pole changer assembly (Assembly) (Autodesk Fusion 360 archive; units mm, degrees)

design "pole changer assembly (Assembly)" references "thimble holder", "combination", "pole changer assembly", "thimble piece", "side panel for middle piece", "wood piece", "cylindrical metal", "underneath rod"
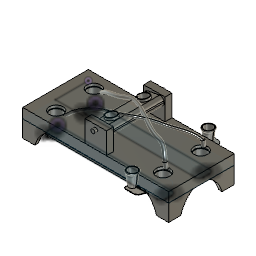
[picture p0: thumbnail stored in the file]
part number: 2026-06-26-15-41-53-289
part number: 2026-06-22-15-23-28-803
part number: 2026-07-01-10-04-10-014
part number: 2026-07-01-10-04-15-208
part number: 2026-07-01-10-11-33-588
component_insert "Component Insert1"
component_insert "Component Insert4"
sketch "Sketch2" plane through (0, 0, 0) normal (0, 1, 0) x axis (1, 0, 0)
  line L1 (27, 0) -> (0, 0)
  line L2 (27, 11.9126) -> (27, 0)
  line L3 (0, 11.9126) -> (27, 11.9126)
  line L4 (0, 0) -> (0, 11.9126)
  point P1 (0, 0)
  point P2 (0, 0)
  point P3 (27, 0)
  point P5 (0, 11.9126)
  horizontal L1
  vertical L2
  horizontal L3
  vertical L4
  coincident P1 P2
  dimension "d5_1" distance P2 P3 = 27
  dimension "d6_1" distance P2 P5 = 11.9126
extrude "Extrude2" new body sketch "Sketch2" along normal blind 71.7804 named "d7_1"
fillet "Fillet1" radius 5 named "d10_1"
sketch "Sketch3" plane through (0, 0, 0) normal (0, -1, 0) x axis (1, 0, 0)
  line L1 (27, -5) -> (27, -6.9126)
  line L2 (5, 0) -> (22, 0)
  line L3 (0, -6.9126) -> (0, -5)
  line L4 (22, -11.9126) -> (5, -11.9126)
  line L5 (22, 0) -> (5, 0)
  line L6 (0, -5) -> (0, -6.9126)
  line L7 (5, -11.9126) -> (22, -11.9126)
  line L8 (27, -6.9126) -> (27, -5)
  line L9 (22, -6.9126) -> (5, -5)
  line L10 (5, -6.9126) -> (22, -6.9126)
  line L11 (22, -5) -> (5, -6.9126)
  line L12 (13.5, 0) -> (13.5, -5.9563)
  line L13 (13.5, -3.341) -> (13.5, 0)
  arc A1 centre (22, -6.9126) radius 5 clockwise from (27, -6.9126) to (22, -11.9126)
  arc A2 centre (22, -5) radius 5 clockwise from (22, 0) to (27, -5)
  arc A3 centre (5, -5) radius 5 clockwise from (0, -5) to (5, 0)
  arc A4 centre (5, -6.9126) radius 5 clockwise from (5, -11.9126) to (0, -6.9126)
  arc A5 centre (5, -5) radius 5 clockwise from (0, -5) to (5, 0)
  arc A6 centre (5, -6.9126) radius 5 clockwise from (5, -11.9126) to (0, -6.9126)
  arc A7 centre (22, -6.9126) radius 5 clockwise from (27, -6.9126) to (22, -11.9126)
  arc A8 centre (22, -5) radius 5 clockwise from (22, 0) to (27, -5)
  circle C1 centre (13.5144, -4.6679) radius 1.327
  point P17 (5, -5)
  point P26 (5, -5)
  point P23 (22, -6.9126)
  point P27 (22, -6.9126)
  point P20 (5, -6.9126)
  point P28 (5, -6.9126)
  point P25 (22, -5)
  point P29 (22, -5)
  point P30 (13.5, -5.9563)
  point P31 (13.5, 0)
  point P32 (13.5, -3.341)
  coincident P17 P26
  coincident P23 P27
  coincident P20 P28
  coincident P25 P29
  midpoint L11 P30
  midpoint L5 P31
  perpendicular L5 L13
  coincident P32 C1
  dimension "d11_1" distance P31 P32 = 3.341
  dimension "d12_1" diameter C1 = 2.654
sketch "Sketch4" plane through (0, 71.7804, 0) normal (0, 1, 0) x axis (-1, 0, 0)
  line L1 (-5, -11.9126) -> (-22, -11.9126)
  line L2 (0, -5) -> (0, -6.9126)
  line L3 (-22, 0) -> (-5, 0)
  line L4 (-27, -6.9126) -> (-27, -5)
  line L5 (-5, -6.9126) -> (-22, -5)
  line L6 (-5, -5) -> (-5, -6.9126)
  line L7 (-22, -6.9126) -> (-5, -5)
  line L8 (-13.5, 0) -> (-13.5, -5.9563)
  line L9 (-13.5, -3.341) -> (-13.5, 0)
  arc A1 centre (-22, -6.9126) radius 5 clockwise from (-22, -11.9126) to (-27, -6.9126)
  arc A2 centre (-5, -6.9126) radius 5 clockwise from (0, -6.9126) to (-5, -11.9126)
  arc A3 centre (-5, -5) radius 5 clockwise from (-5, 0) to (0, -5)
  arc A4 centre (-22, -5) radius 5 clockwise from (-27, -5) to (-22, 0)
  circle C1 centre (-13.5144, -4.6679) radius 1.327
  point P13 (-22, -5)
  point P14 (-22, -5)
  point P7 (-5, -6.9126)
  point P15 (-5, -6.9126)
  point P10 (-5, -5)
  point P16 (-5, -5)
  point P4 (-22, -6.9126)
  point P17 (-22, -6.9126)
  point P18 (-13.5, -5.9563)
  point P19 (-13.5, 0)
  point P20 (-13.5, -3.341)
  coincident P13 P14
  coincident P7 P15
  coincident P10 P16
  coincident P4 P17
  midpoint L5 P18
  midpoint L3 P19
  perpendicular L3 L9
  coincident P20 C1
  dimension "d15" distance P19 P20 = 3.341
  dimension "d16" diameter C1 = 2.654
sketch "Sketch5" plane through (0, 0, 0) normal (0, 0, 1) x axis (-1, 0, 0)
  line L1 (-22, -71.7804) -> (-22, 0)
  line L2 (-5, -71.7804) -> (-22, -71.7804)
  line L3 (-5, 0) -> (-5, -71.7804)
  line L4 (-22, 0) -> (-5, 0)
  line L5 (-13.5, -6) -> (-13.5, 0)
  line L6 (-13.5, -65.7804) -> (-13.5, -71.7804)
  circle C1 centre (-13.5, -13.5) radius 7.5
  circle C2 centre (-13.5, -58.2804) radius 7.5
  circle C3 centre (-13.5, -13.5) radius 6.5
  circle C4 centre (-13.5, -58.2804) radius 6.5
  point P6 (-13.5, 0)
  point P8 (-13.5, -71.7804)
  point P7 (-13.5, -6)
  point P9 (-13.5, -65.7804)
  midpoint L4 P6
  perpendicular L4 L5
  midpoint L2 P8
  perpendicular L2 L6
  coincident P7 C1
  coincident P9 C2
  concentric C1 C3
  concentric C2 C4
  dimension "d19" distance P8 P9 = 6
  dimension "d20" diameter C1 = 15
  dimension "d21" diameter C2 = 15
  dimension "d22" diameter C3 = 13
  dimension "d23" diameter C4 = 13
extrude "Extrude5" add sketch "Sketch5" profile of C1 C2 C3 C4 along normal blind 3 named "d24_1"
extrude "Extrude6" cut of existing geometry blind -6 named "d26_1"
component_insert "Component Insert6"
component_insert "Component Insert7"
component_insert "Component Insert8"
component_insert "Component Insert9"
component_insert "Component Insert10"
component_insert "Component Insert11"
component_insert "Component Insert12"
component_insert "Component Insert13"
position "Position1"
sketch "Sketch1" plane through (0, 0, -13.716) normal (0, 0, -1) x axis (1, 0, 0)
  line L1 (0, 91.44) -> (203.2, 91.44)
  line L2 (0, 0) -> (0, 91.44)
  line L3 (203.2, 0) -> (0, 0)
  line L4 (203.2, 91.44) -> (203.2, 0)
  line L5 (0, 45.72) -> (0, 0)
  line L6 (38, 45.72) -> (0, 45.72)
  circle C1 centre (27.2669, 19.4754) radius 9.525
  circle C2 centre (175.9331, 19.4754) radius 9.525
  circle C3 centre (175.9331, 71.9646) radius 9.525
  circle C4 centre (27.2669, 71.9646) radius 9.525
  point P1 (0, 0)
  point P10 (0, 0)
  point P11 (0, 45.72)
  point P12 (38, 45.72)
  coincident P1 P10
  perpendicular L3 L5
  perpendicular L5 L6
  dimension "d1" distance P10 P11 = 45.72
  dimension "d2" distance P11 P12 = 38
component_insert "Component Insert14"
component_insert "Component Insert15"
position "Position2"
sketch "Sketch2" plane through (0, 0, 0) normal (0, 0, 1) x axis (-1, 0, 0)
  line L1 (-203.2, 91.44) -> (0, 91.44)
  line L2 (-203.2, 0) -> (-203.2, 91.44)
  line L3 (0, 0) -> (-203.2, 0)
  line L4 (0, 91.44) -> (0, 0)
  line L5 (-25.5453, 9.5513) -> (-177.6547, 9.5513)
  line L6 (-19.5453, 23.3887) -> (-19.5453, 15.5513)
  line L7 (-177.6547, 29.3887) -> (-25.5453, 29.3887)
  line L8 (-183.6547, 15.5513) -> (-183.6547, 23.3887)
  line L9 (-183.6547, 23.3887) -> (-183.6547, 15.5513)
  line L10 (-25.5453, 29.3887) -> (-177.6547, 29.3887)
  line L11 (-19.5453, 15.5513) -> (-19.5453, 23.3887)
  line L12 (-177.6547, 9.5513) -> (-25.5453, 9.5513)
  line L13 (0, 91.44) -> (-203.2, 91.44)
  line L14 (0, 0) -> (0, 91.44)
  line L15 (-203.2, 0) -> (0, 0)
  line L16 (-203.2, 91.44) -> (-203.2, 0)
  curve K1 (-175.9331, 71.9646) -> (-27.2669, 19.4754)
  curve K2 (-27.2669, 71.9646) -> (-175.9331, 19.4755)
  curve K3 (-128.5697, 42.4076) -> (-150.1136, 28.6028)
  curve K4 (-160.0793, 60.7438) -> (-134.7391, 51.89)
  curve K5 (-141.9601, 34.3106) -> (-176.1345, 18.4891)
  circle C1 centre (-27.2669, 19.4754) radius 9.525
  circle C2 centre (-27.2669, 71.9646) radius 9.525
  circle C3 centre (-175.9331, 19.4754) radius 9.525
  circle C4 centre (-175.9331, 71.9646) radius 9.525
  circle C5 centre (-27.2669, 19.4754) radius 2.5
  circle C6 centre (-175.9331, 71.9646) radius 2.5
  circle C7 centre (-27.2669, 19.4754) radius 8.525
  circle C8 centre (-27.2669, 19.4754) radius 9.525
  arc A1 centre (-177.6547, 15.5513) radius 6 clockwise from (-177.6547, 9.5513) to (-183.6547, 15.5513)
  arc A2 centre (-25.5453, 15.5513) radius 6 clockwise from (-19.5453, 15.5513) to (-25.5453, 9.5513)
  arc A3 centre (-25.5453, 23.3887) radius 6 clockwise from (-25.5453, 29.3887) to (-19.5453, 23.3887)
  arc A4 centre (-177.6547, 23.3887) radius 6 clockwise from (-183.6547, 23.3887) to (-177.6547, 29.3887)
  arc A5 centre (-177.6547, 15.5513) radius 6 clockwise from (-177.6547, 9.5513) to (-183.6547, 15.5513)
  arc A6 centre (-177.6547, 23.3887) radius 6 clockwise from (-183.6547, 23.3887) to (-177.6547, 29.3887)
  arc A7 centre (-25.5453, 23.3887) radius 6 clockwise from (-25.5453, 29.3887) to (-19.5453, 23.3887)
  arc A8 centre (-25.5453, 15.5513) radius 6 clockwise from (-19.5453, 15.5513) to (-25.5453, 9.5513)
  circle C9 centre (-27.2669, 19.4754) radius 9.525
  circle C10 centre (-27.2669, 19.4754) radius 8.525
  circle C11 centre (-27.2669, 19.4754) radius 8.525
  circle C12 centre (-27.2669, 19.4754) radius 9.525
  circle C13 centre (-27.2669, 19.4754) radius 9.525
  circle C14 centre (-27.2669, 19.4754) radius 9.525
  circle C15 centre (-27.2669, 19.4754) radius 9.525
  circle C16 centre (-27.2669, 19.4754) radius 9.525
  circle C17 centre (-175.9331, 19.4754) radius 9.525
  circle C18 centre (-175.9331, 71.9646) radius 9.525
  circle C19 centre (-27.2669, 71.9646) radius 9.525
  circle C20 centre (-175.9331, 19.4754) radius 2.5
  circle C21 centre (-27.2669, 71.9646) radius 2.5
  point P10 (-27.2669, 19.4754)
  point P53 (-27.2669, 19.4754)
  point P11 (-175.9331, 71.9646)
  point P59 (-175.9331, 71.9646)
  point P60 (-175.9331, 19.4754)
  point P62 (-175.9331, 19.4755)
  point P61 (-27.2669, 71.9646)
  point P69 (-27.2669, 71.9646)
  point P64 (-139.3417, 35.5052)
  point P57 (-147.4092, 56.3169)
  point P63 (-159.0473, 26.3999)
  concentric C1 C5
  concentric C4 C6
  coincident P10 P53
  coincident P11 P59
  concentric C3 C20
  concentric C2 C21
  coincident P60 P62
  coincident P61 P69
  midpoint P64 K3
  midpoint P57 K4
  midpoint P63 K5
  dimension "d3" diameter C5 = 5
  dimension "d4" diameter C6 = 5
  dimension "d5" diameter C20 = 5
  dimension "d6" diameter C21 = 5
loft "Loft2" sketch "Sketch2"
loft "Loft3" sketch "Sketch2"
extrude "Extrude1" add sketch "Sketch2" profile of C21 against normal blind 8
extrude "Extrude2" add sketch "Sketch2" profile of C5 C20 against normal blind 8
extrude "Extrude3" add sketch "Sketch2" profile of C6 against normal blind 8
component_insert "Component Insert16"
position "Position3"
mirror_component "MirrorComponent1"
derived_instance "DerivedInstance1"
sketch "Sketch3" plane through (0, -81.6102, 0) normal (0, -1, 0) x axis (1, 0, 0)
  line L1 (115.1, 21.9126) -> (115.1, 20)
  line L2 (93.1, 26.9126) -> (110.1, 26.9126)
  line L3 (88.1, 20) -> (88.1, 21.9126)
  line L4 (110.1, 15) -> (93.1, 15)
  circle C1 centre (101.6037, 25.1585) radius 1.3313
  arc A1 centre (110.1, 20) radius 5 clockwise from (115.1, 20) to (110.1, 15)
  arc A2 centre (110.1, 21.9126) radius 5 clockwise from (110.1, 26.9126) to (115.1, 21.9126)
  arc A3 centre (93.1, 21.9126) radius 5 clockwise from (88.1, 21.9126) to (93.1, 26.9126)
  arc A4 centre (93.1, 20) radius 5 clockwise from (93.1, 15) to (88.1, 20)
sketch "Sketch4" plane through (0, -9.8298, 0) normal (0, 1, 0) x axis (-1, 0, 0)
  line L1 (-93.1, 15) -> (-110.1, 15)
  line L2 (-88.1, 21.9126) -> (-88.1, 20)
  line L3 (-110.1, 26.9126) -> (-93.1, 26.9126)
  line L4 (-115.1, 20) -> (-115.1, 21.9126)
  circle C1 centre (-101.6, 25.15) radius 1.35
  arc A1 centre (-110.1, 20) radius 5 clockwise from (-110.1, 15) to (-115.1, 20)
  arc A2 centre (-93.1, 20) radius 5 clockwise from (-88.1, 20) to (-93.1, 15)
  arc A3 centre (-93.1, 21.9126) radius 5 clockwise from (-93.1, 26.9126) to (-88.1, 21.9126)
  arc A4 centre (-110.1, 21.9126) radius 5 clockwise from (-115.1, 21.9126) to (-110.1, 26.9126)
as_built_joint "As-built5" OffsetX 0 OffsetY 0 OffsetZ 0 AngleZ 0 RotateMinimum -8 RotateMaximum 8
component_from_bodies "Body->Comp1"
component_from_bodies "Body->Comp2"
as_built_joint "As-built8"
copy_paste "CutPaste1"
copy_paste "CutPaste2"
sketch "Sketch5" plane through (0, -91.2914, 0) normal (0, -1, 0) x axis (1, 0, 0)
  line L1 (86.6775, 0) -> (86.6775, 29.845)
  line L2 (116.5225, 0) -> (86.6775, 0)
  line L3 (116.5225, 29.845) -> (116.5225, 0)
  line L4 (86.6775, 29.845) -> (116.5225, 29.845)
  circle C1 centre (101.6, 23.837) radius 2.667
  circle C2 centre (101.6, 23.837) radius 1.35
  concentric C1 C2
extrude "Extrude6" new body sketch "Sketch5" profile of C1 C2 along normal blind 6
sketch "Sketch6" plane through (0, -0.1486, 0) normal (0, 1, 0) x axis (-1, 0, 0)
  line L1 (-53.6775, 72.39) -> (-53.6775, 42.545)
  line L2 (-83.5225, 72.39) -> (-53.6775, 72.39)
  line L3 (-83.5225, 42.545) -> (-83.5225, 72.39)
  line L4 (-53.6775, 42.545) -> (-83.5225, 42.545)
  circle C1 centre (-68.6, 66.382) radius 2.667
  circle C2 centre (-68.6, 66.382) radius 1.35
  concentric C1 C2
extrude "Extrude7" new body sketch "Sketch6" profile of C1 C2 along normal blind 6
extrude "Extrude8" cut of existing geometry blind -2
extrude "Extrude9" cut of existing geometry blind -2
component_insert "Component Insert17"
move "Move1"
move "Move2"
component_insert "Component Insert18"
position "Position4"
component_insert "Component Insert19"
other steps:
base_feature "Base Feature1"
base_feature "Base Feature1"
derived_base_feature "Derived Base Feature" sketch "Sketch2"
create_component "CreateComponent1"
create_component "CreateComponent2"
create_component "CreateComponent3"
reparent_decal "ReparentDecal2"
remove_body "RemoveBody2"
create_component "CreateComponent4"
remove_instance "RemoveInstance1"
remove_instance "RemoveInstance2"
reparent_decal "ReparentDecal3"
remove_body "RemoveBody3"

design "Side panel for the top of Pole Changer" references "autodesk 3ax table xy head z"
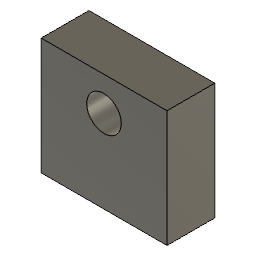
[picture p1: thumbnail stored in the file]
part number: 2026-03-06-14-36-18-397
sketch "Sketch1" plane through (0, 0, 0) normal (0, 0, 1) x axis (1, 0, 0)
  line L1 (32.385, 0) -> (0, 0)
  line L2 (32.385, 12.319) -> (32.385, 0)
  line L3 (0, 12.319) -> (32.385, 12.319)
  line L4 (0, 0) -> (0, 12.319)
  point P1 (0, 0)
  point P2 (0, 0)
  point P3 (32.385, 0)
  point P5 (0, 12.319)
  horizontal L1
  vertical L2
  horizontal L3
  vertical L4
  coincident P1 P2
  dimension "d1" distance P2 P3 = 32.385
  dimension "d2" distance P2 P5 = 12.319
extrude "Extrude1" new body sketch "Sketch1" along normal blind 30.0482
sketch "Sketch2" plane through (0, 0, 0) normal (0, -1, 0) x axis (1, 0, 0)
  line L1 (32.385, 0) -> (0, 0)
  line L2 (32.385, 30.0482) -> (32.385, 0)
  line L3 (0, 30.0482) -> (32.385, 30.0482)
  line L4 (0, 0) -> (0, 30.0482)
  circle C1 centre (16.1726, 21.3291) radius 4.445
  dimension "d5" diameter C1 = 8.89
extrude "Extrude2" cut sketch "Sketch2" profile of C1 against normal blind 12.319

design "cylindrical metal"
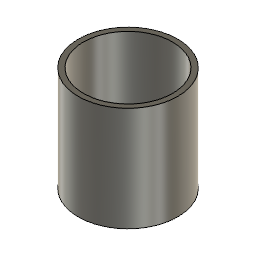
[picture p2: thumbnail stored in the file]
part number: 2026-06-29-10-16-31-492
sketch "Sketch1" plane through (0, 0, 0) normal (0, 0, 1) x axis (1, 0, 0)
  circle C1 centre (0, 0) radius 9.525
  point P1 (0, 0)
  point P2 (0, 0)
  coincident P1 P2
  dimension "d1" diameter C1 = 19.05
extrude "Extrude1" new body sketch "Sketch1" along normal blind 20
shell "Shell1" innerThickness 1

design "thimble piece"
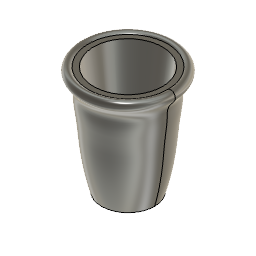
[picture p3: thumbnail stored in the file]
part number: 2026-06-22-15-23-28-803
sketch "Sketch2" plane through (0, 0, 0) normal (0, 1, 0) x axis (1, 0, 0)
  line L1 (17.6024, 0) -> (0, 0)
  line L2 (17.6024, -7) -> (17.6024, 0)
  curve K1 (22, -13) -> (17.6024, -7)
  curve K2 (21.2743, -12.5102) -> (16.7269, -7.4605)
  line L3 (16.7269, -7.4605) -> (16.7269, -0.8755)
  line L4 (16.7269, -0.8755) -> (0.8755, -0.8755)
  line L5 (0, 0) -> (0.8755, -0.8755)
  line L6 (22, -13) -> (21.2743, -12.5102)
  point P1 (0, 0)
  point P2 (0, 0)
  point P3 (17.6024, 0)
  point P4 (17.6024, -7)
  coincident P1 P2
  perpendicular L1 L2
  dimension "d1" distance P3 P4 = 7
  dimension "d2" = 0.8755
sketch "Sketch4" plane through (0, 0, 0) normal (0, 1, 0) x axis (1, 0, 0)
  line L1 (4.655, 0) -> (0, 0)
  curve K1 (6.9446, -18.8982) -> (4.655, 0)
  line L2 (6.0248, -18.8982) -> (6.9446, -18.8982)
  line L3 (3.5953, -1.1464) -> (6.0248, -18.8982)
  line L4 (0, -1.1464) -> (3.5953, -1.1464)
  line L5 (0, 0) -> (0, -1.1464)
  point P1 (0, 0)
  point P2 (0, 0)
  coincident P1 P2
  horizontal L1
  horizontal L2
  parallel L1 L4
  perpendicular L1 L5
revolve "Revolve2" sketch "Sketch4" AlongAngle 360

design "side panel for middle piece"
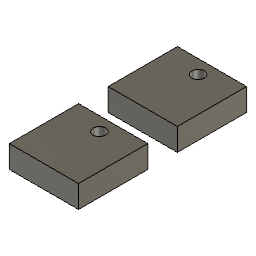
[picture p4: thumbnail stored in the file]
part number: 2026-06-23-11-54-25-800
sketch "Sketch1" plane through (0, 0, 0) normal (0, 1, 0) x axis (1, 0, 0)
  line L1 (29.845, 0) -> (0, 0)
  line L2 (29.845, 29.845) -> (29.845, 0)
  line L3 (0, 29.845) -> (29.845, 29.845)
  line L4 (0, 0) -> (0, 29.845)
  point P1 (0, 0)
  point P2 (0, 0)
  point P3 (29.845, 0)
  point P5 (0, 29.845)
  horizontal L1
  vertical L2
  horizontal L3
  vertical L4
  coincident P1 P2
  dimension "d1" distance P2 P3 = 29.845
  dimension "d2" distance P2 P5 = 29.845
extrude "Extrude1" new body sketch "Sketch1" along normal blind 9.7028
sketch "Sketch2" plane through (0, 0, 0) normal (0, -1, 0) x axis (1, 0, 0)
  line L1 (0, -29.845) -> (0, 0)
  line L2 (29.845, -29.845) -> (0, -29.845)
  line L3 (29.845, 0) -> (29.845, -29.845)
  line L4 (0, 0) -> (29.845, 0)
  line L5 (29.845, -29.845) -> (0, 0)
  line L6 (0, -29.845) -> (29.845, 0)
  line L7 (14.9225, 0) -> (14.9225, -14.9225)
  line L8 (14.9225, -3.341) -> (14.9225, 0)
  circle C1 centre (14.9225, -6.008) radius 2.667
  point P1 (0, 0)
  point P6 (0, 0)
  point P4 (29.845, -29.845)
  point P7 (29.845, -29.845)
  point P5 (29.845, 0)
  point P8 (29.845, 0)
  point P3 (0, -29.845)
  point P9 (0, -29.845)
  point P10 (14.9225, -14.9225)
  point P11 (14.9225, 0)
  point P12 (14.9225, -3.341)
  coincident P1 P6
  coincident P4 P7
  coincident P5 P8
  coincident P3 P9
  midpoint L6 P10
  midpoint L4 P11
  perpendicular L4 L8
  coincident P12 C1
  dimension "d5" distance P11 P12 = 3.341
  dimension "d6" diameter C1 = 5.334
extrude "Extrude2" cut sketch "Sketch2" profile of L7 C1 against normal blind 27
sketch "Sketch3" plane through (0, 0, 0) normal (0, 1, 0) x axis (1, 0, 0)
copy_paste_bodies "CopyPasteBodies1"
move "Move1"
move "Move2"
move "Move3"
move "Move4"
move "Move5"
move "Move6"
move "Move7"
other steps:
base_feature "Base Feature"

design "thimble holder"
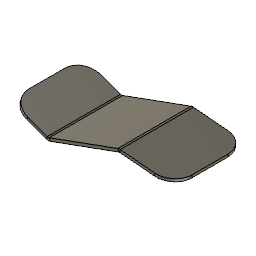
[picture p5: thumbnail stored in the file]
part number: 2026-06-23-10-44-33-506
parameter "d6" = 0.762
sketch "Sketch1" plane through (0, 0, 0) normal (0, 0, 1) x axis (1, 0, 0)
  line L1 (40.4406, 0) -> (5, 0)
  line L2 (45.4406, -14.558) -> (45.4406, -5)
  line L3 (5, -19.558) -> (40.4406, -19.558)
  line L4 (0, -5) -> (0, -14.558)
  arc A1 centre (5, -5) radius 5 clockwise from (0, -5) to (5, 0)
  arc A2 centre (5, -14.558) radius 5 clockwise from (5, -19.558) to (0, -14.558)
  arc A3 centre (40.4406, -14.558) radius 5 clockwise from (45.4406, -14.558) to (40.4406, -19.558)
  arc A4 centre (40.4406, -5) radius 5 clockwise from (40.4406, 0) to (45.4406, -5)
  point P1 (0, 0)
  point P2 (0, 0)
  point P4 (0, -19.558)
  point P3 (45.4406, 0)
  horizontal L1
  vertical L2
  horizontal L3
  vertical L4
  coincident P1 P2
  coincident P2 L1
  coincident P2 L4
  tangent L1 A1
  tangent L4 A1
  coincident P4 L3
  coincident P4 L4
  tangent L3 A2
  tangent L4 A2
  equal A1 A2
  tangent L2 A3
  tangent L3 A3
  equal A1 A3
  coincident P3 L1
  coincident P3 L2
  tangent L1 A4
  tangent L2 A4
  equal A1 A4
  dimension "d1" distance P2 P3 = 45.4406
  dimension "d2" distance P2 P4 = 19.558
  dimension "d3" radius A1 = 5
extrude "Extrude1" new body sketch "Sketch1" along normal blind 0.762
sketch "Sketch2" plane through (0, 0, 0) normal (0, 0, 1) x axis (1, 0, 0)
step "ConvertToSheetMetal"
sketch "Sketch3" plane through (0, 0, 0.762) normal (0, 0, 1) x axis (-1, 0, 0)
  line L1 (-45.4406, 5) -> (-45.4406, 14.558)
  line L2 (-5, 0) -> (-40.4406, 0)
  line L3 (0, 14.558) -> (0, 5)
  line L4 (-40.4406, 19.558) -> (-5, 19.558)
  line L5 (-11.2867, 0) -> (-11.2867, 19.558)
  line L6 (-30.7215, 0) -> (-30.7215, 19.558)
  arc A1 centre (-40.4406, 14.558) radius 5 clockwise from (-45.4406, 14.558) to (-40.4406, 19.558)
  arc A2 centre (-40.4406, 5) radius 5 clockwise from (-40.4406, 0) to (-45.4406, 5)
  arc A3 centre (-5, 5) radius 5 clockwise from (0, 5) to (-5, 0)
  arc A4 centre (-5, 14.558) radius 5 clockwise from (-5, 19.558) to (0, 14.558)
  point P14 (-11.2867, 19.558)
  point P15 (-11.2867, 0)
  point P16 (-30.7215, 19.558)
  point P17 (-30.7215, 0)
  coincident L4 P14
  coincident L2 P15
  perpendicular L2 L5
  coincident L4 P16
  coincident L2 P17
  perpendicular L2 L6
step "Fold" BendAngle -25 BendAngle 40
move "Move2"

design "wood piece"
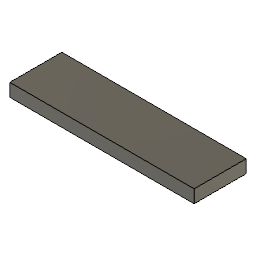
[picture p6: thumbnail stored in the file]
part number: 2026-06-29-10-46-20-872
sketch "Sketch1" plane through (0, 0, 0) normal (0, 0, 1) x axis (1, 0, 0)
  line L1 (127.2, 0) -> (0, 0)
  line L2 (127.2, 36) -> (127.2, 0)
  line L3 (0, 36) -> (127.2, 36)
  line L4 (0, 0) -> (0, 36)
  point P1 (0, 0)
  point P2 (0, 0)
  point P3 (127.2, 0)
  point P5 (0, 36)
  horizontal L1
  vertical L2
  horizontal L3
  vertical L4
  coincident P1 P2
  dimension "d1" distance P2 P3 = 127.2
  dimension "d2" distance P2 P5 = 36
extrude "Extrude1" new body sketch "Sketch1" along normal blind 9

design "autodesk 3ax table xy head z"
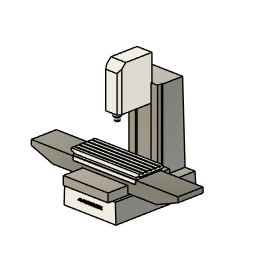
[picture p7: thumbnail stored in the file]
named bodies: "x_axis_table", "y_axis_table", "z_axis_head", "Base"

design "base plate"
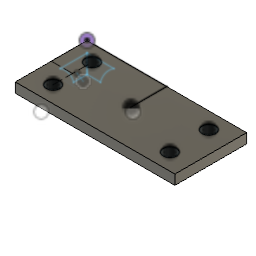
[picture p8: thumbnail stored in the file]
part number: 2026-06-18-10-46-35-977
sketch "Sketch1" plane through (0, 0, 0) normal (0, 0, 1) x axis (1, 0, 0)
  line L1 (203.2, 0) -> (0, 0)
  line L2 (203.2, -91.44) -> (203.2, 0)
  line L3 (0, -91.44) -> (203.2, -91.44)
  line L4 (0, 0) -> (0, -91.44)
  point P1 (0, 0)
  point P2 (0, 0)
  point P3 (203.2, 0)
  point P5 (0, -91.44)
  horizontal L1
  vertical L2
  horizontal L3
  vertical L4
  coincident P1 P2
  dimension "d1" distance P2 P3 = 203.2
  dimension "d2" distance P2 P5 = 91.44
extrude "Extrude1" new body sketch "Sketch1" against normal blind 12.573
sketch "Sketch2" plane through (0, 0, 0) normal (0, 1, 0) x axis (1, 0, 0)
  line L1 (0, 37.5458) -> (0, 14)
  line L2 (17.0307, 37.5458) -> (0, 37.5458)
  line L3 (34.0614, 14) -> (0, 14)
  arc A1 centre (58.4006, 49.5366) radius 43.0726 clockwise from (34.0614, 14) to (17.0307, 37.5458)
  point P2 (0, 14)
  point P3 (0, 37.5458)
  point P4 (17.0307, 37.5458)
  point P5 (34.0614, 14)
  vertical L1
  perpendicular L1 L2
  perpendicular L1 L3
  dimension "d5" distance P2 P3 = 23.5458
  dimension "d6" distance P3 P4 = 17.0307
  dimension "d7" distance P2 P5 = 34.0614
sketch "Sketch4" plane through (0, 0, 0) normal (0, 1, 0) x axis (1, 0, 0)
  dimension "d8" = 23.5458
  dimension "d9" = 17.0307
  dimension "d10" = 34.0614
extrude "Extrude2" new body sketch "Sketch2" against normal blind 12.573
sketch "Sketch6" plane through (0, 0, -37.5458) normal (0, 0, -1) x axis (1, 0, 0)
  line L1 (17.0307, 0) -> (0, 0)
  line L2 (17.0307, 12.573) -> (17.0307, 0)
  line L3 (0, 12.573) -> (17.0307, 12.573)
  line L4 (0, 0) -> (0, 12.573)
  line L5 (12.573, 12.573) -> (0, 0)
  point P1 (0, 0)
  point P6 (0, 0)
  point P7 (12.573, 12.573)
  coincident P1 P6
  coincident L3 P7
copy_paste_bodies "CopyPasteBodies1"
move "Move1"
sketch "Sketch7" plane through (0, 0, -37.5458) normal (0, 0, -1) x axis (1, 0, 0)
  line L1 (5, 22.0307) -> (5, 5)
  line L2 (-7.573, 22.0307) -> (5, 22.0307)
  line L3 (-7.573, 5) -> (-7.573, 22.0307)
  line L4 (5, 5) -> (-7.573, 5)
  line L5 (5, 10) -> (-7.573, 5)
  point P5 (-7.573, 5)
  point P6 (-7.573, 5)
  point P7 (5, 10)
  coincident P5 P6
  coincident L1 P7
extrude "Extrude3" cut sketch "Sketch6" profile of L3 L4 L5 against normal blind 23.546
extrude "Extrude4" cut sketch "Sketch7" profile of L1 L4 L5 against normal blind 23.546
move "Move2"
sketch "Sketch9" plane through (0, 0, 0) normal (0, 0, 1) x axis (1, 0, 0)
  line L1 (27.2669, -20.955) -> (27.2669, -70.485)
  line L2 (0, -45.72) -> (0, 0)
  line L3 (27.2669, -45.72) -> (0, -45.72)
  line L4 (101.6, 0) -> (0, 0)
  line L5 (101.6, -45.72) -> (101.6, 0)
  circle C1 centre (27.2669, -70.485) radius 8.35
  circle C2 centre (27.2669, -20.955) radius 8.35
  circle C3 centre (175.9331, -20.955) radius 8.35
  circle C4 centre (175.9331, -70.485) radius 8.35
  point P2 (27.2669, -70.485)
  point P4 (27.2669, -70.485)
  point P3 (27.2669, -20.955)
  point P5 (27.2669, -20.955)
  point P1 (0, 0)
  point P6 (0, 0)
  point P8 (27.2669, -45.72)
  point P7 (0, -45.72)
  point P9 (101.6, 0)
  point P10 (101.6, -45.72)
  point P11 (175.9331, -20.955)
  coincident P2 P4
  coincident P3 P5
  vertical L1
  coincident P1 P6
  vertical L2
  coincident L1 P8
  perpendicular L1 L3
  symmetric P2 P3 L3
  horizontal L4
  perpendicular L4 L5
  symmetric C1 L5 C4
  symmetric C2 L5 C3
  dimension "d17" diameter C1 = 16.7
  dimension "d18" diameter C2 = 16.7
  dimension "d19" distance P2 P3 = 49.53
  dimension "d20" distance P6 P7 = 45.72
  dimension "d21" distance P6 P9 = 101.6
  dimension "d22" distance P9 P10 = 45.72
  dimension "d23" distance P3 P11 = 148.6662
extrude "Extrude5" cut sketch "Sketch9" profile of C1 C2 C3 C4 against normal blind 7.5
extrude "Extrude6" cut sketch "Sketch9" profile of C1 C2 C3 C4 against normal blind 45
combine "Combine2"
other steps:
base_feature "Base Feature"
step "WorkPlane" RotateAngle -45

design "underneath rod"
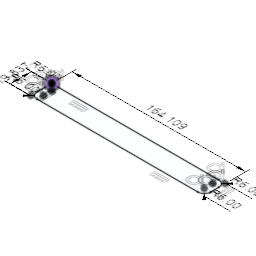
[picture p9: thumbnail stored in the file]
part number: 2026-06-22-13-07-32-892
sketch "Sketch1" plane through (0, 0, 0) normal (0, 0, 1) x axis (1, 0, 0)
  line L1 (158.1094, 0) -> (6, 0)
  line L2 (164.1094, -13.8374) -> (164.1094, -6)
  line L3 (6, -19.8374) -> (158.1094, -19.8374)
  line L4 (0, -6) -> (0, -13.8374)
  arc A1 centre (158.1094, -6) radius 6 clockwise from (158.1094, 0) to (164.1094, -6)
  arc A2 centre (158.1094, -13.8374) radius 6 clockwise from (164.1094, -13.8374) to (158.1094, -19.8374)
  arc A3 centre (6, -13.8374) radius 6 clockwise from (6, -19.8374) to (0, -13.8374)
  arc A4 centre (6, -6) radius 6 clockwise from (0, -6) to (6, 0)
  point P1 (0, 0)
  point P2 (0, 0)
  point P3 (164.1094, 0)
  point P4 (0, -19.8374)
  horizontal L1
  vertical L2
  horizontal L3
  vertical L4
  coincident P1 P2
  coincident P3 L1
  coincident P3 L2
  tangent L1 A1
  tangent L2 A1
  tangent L2 A2
  tangent L3 A2
  coincident P4 L3
  coincident P4 L4
  tangent L3 A3
  tangent L4 A3
  coincident P2 L4
  coincident P2 L1
  tangent L4 A4
  tangent L1 A4
  dimension "d1" distance P2 P3 = 164.1094
  dimension "d2" distance P2 P4 = 19.8374
  dimension "d5" radius A1 = 6
  dimension "d6" radius A2 = 6
  dimension "d7" radius A3 = 6
  dimension "d8" radius A4 = 6
extrude "Extrude2" new body sketch "Sketch1" along normal blind 2.6162
sketch "Sketch2" plane through (0, 0, 0) normal (0, 0, 1) x axis (1, 0, 0)
sketch "Sketch5" plane through (0, 0, 2.6162) normal (0, 0, 1) x axis (-1, 0, 0)
  line L1 (-6, 0) -> (-158.1094, 0)
  line L2 (0, 13.8374) -> (0, 6)
  line L3 (-158.1094, 19.8374) -> (-6, 19.8374)
  line L4 (-164.1094, 6) -> (-164.1094, 13.8374)
  arc A1 centre (-158.1094, 6) radius 6 clockwise from (-158.1094, 0) to (-164.1094, 6)
  arc A2 centre (-6, 6) radius 6 clockwise from (0, 6) to (-6, 0)
  arc A3 centre (-6, 13.8374) radius 6 clockwise from (-6, 19.8374) to (0, 13.8374)
  arc A4 centre (-158.1094, 13.8374) radius 6 clockwise from (-164.1094, 13.8374) to (-158.1094, 19.8374)

design "combination" references "Side panel for the top of Pole Changer", "underneath rod", "base plate"
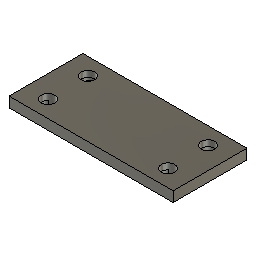
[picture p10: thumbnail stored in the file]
part number: 2026-06-22-14-06-53-231
external_derived "Sketch1"
external_derived "ExternalDerived2"
sketch "Sketch1" plane through (0, 0, -12.573) normal (0, 0, -1) x axis (1, 0, 0)
  line L1 (0, 91.44) -> (203.2, 91.44)
  line L2 (0, 0) -> (0, 91.44)
  line L3 (203.2, 0) -> (0, 0)
  line L4 (203.2, 91.44) -> (203.2, 0)
  line L5 (101.6, 0) -> (203.2, 0)
  line L6 (203.2, 45.72) -> (203.2, 0)
  line L7 (101.6, 45.72) -> (203.2, 45.72)
  line L8 (101.6, 0) -> (101.6, 45.72)
  line L9 (101.6, 25) -> (101.6, 0)
  line L10 (101.6, 91.44) -> (101.6, 45.72)
  line L11 (101.6, 68.58) -> (101.6, 91.44)
  circle C1 centre (175.9331, 20.955) radius 8.35
  circle C2 centre (27.2669, 20.955) radius 8.35
  circle C3 centre (27.2669, 70.485) radius 8.35
  circle C4 centre (175.9331, 70.485) radius 8.35
  point P5 (203.2, 0)
  point P6 (203.2, 0)
  point P7 (101.6, 0)
  point P8 (203.2, 45.72)
  point P10 (101.6, 25)
  point P11 (101.6, 91.44)
  point P12 (101.6, 68.58)
  coincident P5 P6
  midpoint L3 P7
  midpoint L4 P8
  perpendicular L4 L7
  perpendicular L5 L8
  coincident L8 P10
  midpoint L1 P11
  midpoint L10 P12
move "Move1"
align "Align1"
move "Move2"
align "Align2"
move "Move3"
mirror "Mirror1" mirrorStitchTolerance 0.1
move "Move4"
align "Align3"
align "Align4"
move "Move5"
sketch "Sketch4" plane through (0, 0, -12.573) normal (0, 0, -1) x axis (1, 0, 0)
  line L1 (26.6, 68.54) -> (26.6, 91.4)
  circle C1 centre (26.6, 68.54) radius 6.5
  point P3 (26.6, 68.54)
  point P4 (26.6, 68.54)
  point P2 (26.6, 91.4)
  vertical L1
  coincident P3 P4
  dimension "d4" distance P2 P3 = 22.86
  dimension "d5" diameter C1 = 13
extrude "Extrude2" cut of existing geometry blind -20
move "Move6"
move "Move7"
move "Move8"
move "Move9"
move "Move10"
move "Move11"
component_insert "Component Insert"
remove_instance "RemoveInstance1"
move "Move12"
move "Move13"
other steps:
derived_base_feature "Sketch1"
derived_base_feature "Derived Base Feature"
